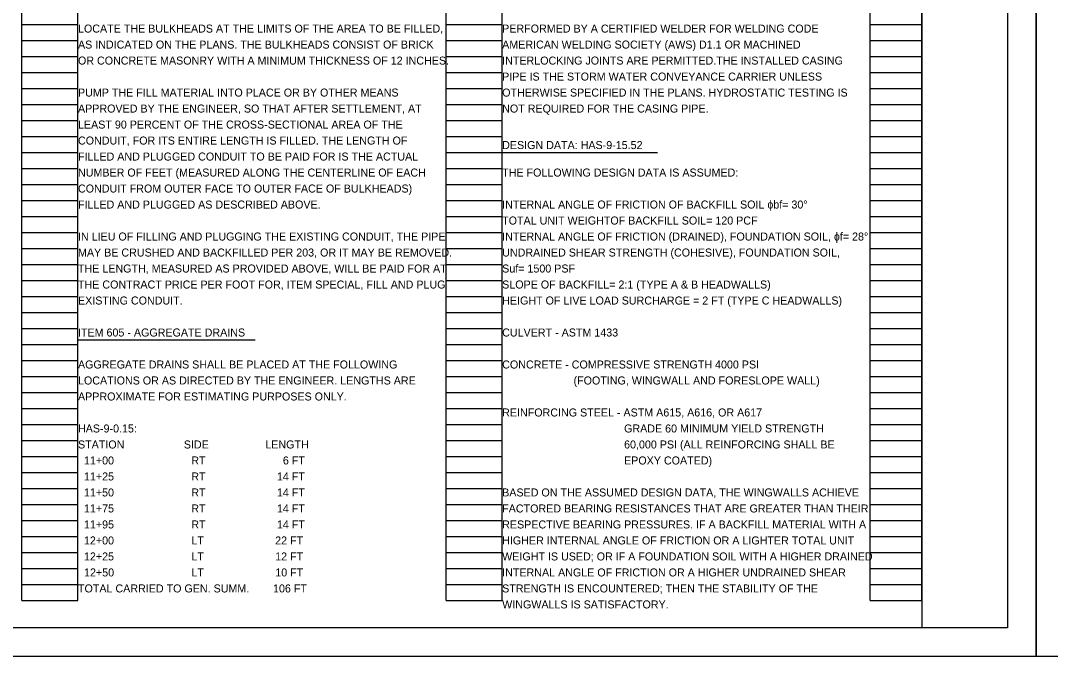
# Model space of a CAD drawing. Extents: x 0 to 102, y 0 to 22.
# Drawn here: x 50.24 to 68.25, y 0 to 11.13 of the extents above; entities that cross this region are included whole.
import ezdxf

# ---------------------------------------------------------------- set-up
doc = ezdxf.new("R2010")
doc.units = 0
doc.layers.add('SC_Scratch1', color=7, linetype='Continuous')
doc.layers.add('SH_Text', color=7, linetype='Continuous')

msp = doc.modelspace()

# ---------------------------------------------------------------- linework, layer by layer
at = {"layer": 'SC_Scratch1'}
for p, q in [((50.26, 0.98), (50.26, 21.14)), ((51.24, 0.98), (51.24, 21.14)), ((57.68, 0.98), (57.68, 21.14)), ((58.66, 0.98), (58.66, 21.14)), ((65.1, 0.98), (65.1, 21.14)), ((66, 0.98), (66, 21.14)), ((50.26, 11.06), (51.24, 11.06)), ((57.68, 11.06), (58.66, 11.06)), ((65.1, 11.06), (66, 11.06)), ((50.26, 10.78), (51.24, 10.78)), ((57.68, 10.78), (58.66, 10.78)), ((65.1, 10.78), (66, 10.78)), ((50.26, 10.5), (51.24, 10.5)), ((57.68, 10.5), (58.66, 10.5)), ((65.1, 10.5), (66, 10.5)), ((50.26, 10.22), (51.24, 10.22)), ((57.68, 10.22), (58.66, 10.22)), ((65.1, 10.22), (66, 10.22)), ((50.26, 9.94), (51.24, 9.94)), ((57.68, 9.94), (58.66, 9.94)), ((65.1, 9.94), (66, 9.94)), ((50.26, 9.66), (51.24, 9.66)), ((57.68, 9.66), (58.66, 9.66)), ((65.1, 9.66), (66, 9.66)), ((50.26, 9.38), (51.24, 9.38)), ((57.68, 9.38), (58.66, 9.38)), ((65.1, 9.38), (66, 9.38)), ((50.26, 9.1), (51.24, 9.1)), ((57.68, 9.1), (58.66, 9.1)), ((65.1, 9.1), (66, 9.1)), ((50.26, 8.82), (51.24, 8.82)), ((57.68, 8.82), (58.66, 8.82)), ((65.1, 8.82), (66, 8.82)), ((50.26, 8.54), (51.24, 8.54)), ((57.68, 8.54), (58.66, 8.54)), ((65.1, 8.54), (66, 8.54)), ((50.26, 8.26), (51.24, 8.26)), ((57.68, 8.26), (58.66, 8.26)), ((65.1, 8.26), (66, 8.26)), ((50.26, 7.98), (51.24, 7.98)), ((57.68, 7.98), (58.66, 7.98)), ((65.1, 7.98), (66, 7.98)), ((50.26, 7.7), (51.24, 7.7)), ((57.68, 7.7), (58.66, 7.7)), ((65.1, 7.7), (66, 7.7)), ((50.26, 7.42), (51.24, 7.42)), ((57.68, 7.42), (58.66, 7.42)), ((65.1, 7.42), (66, 7.42)), ((50.26, 7.14), (51.24, 7.14)), ((57.68, 7.14), (58.66, 7.14)), ((65.1, 7.14), (66, 7.14)), ((50.26, 6.86), (51.24, 6.86)), ((57.68, 6.86), (58.66, 6.86)), ((65.1, 6.86), (66, 6.86)), ((50.26, 6.58), (51.24, 6.58)), ((57.68, 6.58), (58.66, 6.58)), ((65.1, 6.58), (66, 6.58)), ((50.26, 6.3), (51.24, 6.3)), ((57.68, 6.3), (58.66, 6.3)), ((65.1, 6.3), (66, 6.3)), ((50.26, 6.02), (51.24, 6.02)), ((57.68, 6.02), (58.66, 6.02)), ((65.1, 6.02), (66, 6.02)), ((50.26, 5.74), (51.24, 5.74)), ((57.68, 5.74), (58.66, 5.74)), ((65.1, 5.74), (66, 5.74)), ((50.26, 5.46), (51.24, 5.46)), ((57.68, 5.46), (58.66, 5.46)), ((65.1, 5.46), (66, 5.46)), ((50.26, 5.18), (51.24, 5.18)), ((57.68, 5.18), (58.66, 5.18)), ((65.1, 5.18), (66, 5.18)), ((50.26, 4.9), (51.24, 4.9)), ((57.68, 4.9), (58.66, 4.9)), ((65.1, 4.9), (66, 4.9)), ((50.26, 4.62), (51.24, 4.62)), ((57.68, 4.62), (58.66, 4.62)), ((65.1, 4.62), (66, 4.62)), ((50.26, 4.34), (51.24, 4.34)), ((57.68, 4.34), (58.66, 4.34)), ((65.1, 4.34), (66, 4.34)), ((50.26, 4.06), (51.24, 4.06)), ((57.68, 4.06), (58.66, 4.06)), ((65.1, 4.06), (66, 4.06)), ((50.26, 3.78), (51.24, 3.78)), ((57.68, 3.78), (58.66, 3.78)), ((65.1, 3.78), (66, 3.78)), ((50.26, 3.5), (51.24, 3.5)), ((57.68, 3.5), (58.66, 3.5)), ((65.1, 3.5), (66, 3.5)), ((50.26, 3.22), (51.24, 3.22)), ((57.68, 3.22), (58.66, 3.22)), ((65.1, 3.22), (66, 3.22)), ((50.26, 2.94), (51.24, 2.94)), ((57.68, 2.94), (58.66, 2.94)), ((65.1, 2.94), (66, 2.94)), ((50.26, 2.66), (51.24, 2.66)), ((57.68, 2.66), (58.66, 2.66)), ((65.1, 2.66), (66, 2.66)), ((50.26, 2.38), (51.24, 2.38)), ((57.68, 2.38), (58.66, 2.38)), ((65.1, 2.38), (66, 2.38)), ((50.26, 2.1), (51.24, 2.1)), ((57.68, 2.1), (58.66, 2.1)), ((65.1, 2.1), (66, 2.1)), ((50.26, 1.82), (51.24, 1.82)), ((57.68, 1.82), (58.66, 1.82)), ((65.1, 1.82), (66, 1.82)), ((50.26, 1.54), (51.24, 1.54)), ((57.68, 1.54), (58.66, 1.54)), ((65.1, 1.54), (66, 1.54)), ((50.26, 1.26), (51.24, 1.26)), ((57.68, 1.26), (58.66, 1.26)), ((65.1, 1.26), (66, 1.26)), ((50.26, 0.98), (51.24, 0.98)), ((57.68, 0.98), (58.66, 0.98)), ((65.1, 0.98), (66, 0.98)), ((68, 0), (68, 0))]:
    msp.add_line(p, q, dxfattribs=at)
for points in [[(34, 22), (68, 22), (68, 0), (34, 0)], [(68, 22), (102, 22), (102, 0), (68, 0)], [(34.5, 21.5), (67.5, 21.5), (67.5, 0.5), (34.5, 0.5)], [(35.5, 21.5), (66, 21.5), (66, 0.5), (35.5, 0.5)]]:
    msp.add_lwpolyline(points, close=True, dxfattribs=at)
at = {"layer": 'SH_Text'}
for p, q in [((58.66, 8.82), (61.377, 8.82)), ((51.24, 5.539), (54.339, 5.539))]:
    msp.add_line(p, q, dxfattribs=at)

# ---------------------------------------------------------------- texts
for s, p in [('LOCATE THE BULKHEADS AT THE LIMITS OF THE AREA TO BE FILLED,', (51.24, 10.92)), ('PERFORMED BY A CERTIFIED WELDER FOR WELDING CODE ', (58.66, 10.92)), ('AS INDICATED ON THE PLANS. THE BULKHEADS CONSIST OF BRICK', (51.24, 10.64)), ('AMERICAN WELDING SOCIETY (AWS) D1.1 OR MACHINED ', (58.66, 10.64)), ('OR CONCRETE MASONRY WITH A MINIMUM THICKNESS OF 12 INCHES.', (51.24, 10.36)), ('INTERLOCKING JOINTS ARE PERMITTED.THE INSTALLED CASING ', (58.66, 10.36)), ('PIPE IS THE STORM WATER CONVEYANCE CARRIER UNLESS ', (58.66, 10.08)), ('PUMP THE FILL MATERIAL INTO PLACE OR BY OTHER MEANS', (51.24, 9.8)), ('OTHERWISE SPECIFIED IN THE PLANS. HYDROSTATIC TESTING IS ', (58.66, 9.8)), ('APPROVED BY THE ENGINEER, SO THAT AFTER SETTLEMENT, AT', (51.24, 9.52)), ('NOT REQUIRED FOR THE CASING PIPE.', (58.66, 9.52)), ('LEAST 90 PERCENT OF THE CROSS-SECTIONAL AREA OF THE', (51.24, 9.24)), ('CONDUIT, FOR ITS ENTIRE LENGTH IS FILLED. THE LENGTH OF', (51.24, 8.96)), ('DESIGN DATA: HAS-9-15.52 ', (58.66, 8.881)), ('FILLED AND PLUGGED CONDUIT TO BE PAID FOR IS THE ACTUAL', (51.24, 8.68)), ('NUMBER OF FEET (MEASURED ALONG THE CENTERLINE OF EACH', (51.24, 8.4)), ('THE FOLLOWING DESIGN DATA IS ASSUMED:', (58.66, 8.4)), ('CONDUIT FROM OUTER FACE TO OUTER FACE OF BULKHEADS)', (51.24, 8.12)), ('FILLED AND PLUGGED AS DESCRIBED ABOVE.', (51.24, 7.84)), ('INTERNAL ANGLE OF FRICTION OF BACKFILL SOIL ɸbf= 30°', (58.66, 7.84)), ('TOTAL UNIT WEIGHTOF BACKFILL SOIL= 120 PCF', (58.66, 7.56)), ('IN LIEU OF FILLING AND PLUGGING THE EXISTING CONDUIT, THE PIPE ', (51.24, 7.28)), ('INTERNAL ANGLE OF FRICTION (DRAINED), FOUNDATION SOIL, ɸf= 28°', (58.66, 7.28)), ('MAY BE CRUSHED AND BACKFILLED PER 203, OR IT MAY BE REMOVED. ', (51.24, 7)), ('UNDRAINED SHEAR STRENGTH (COHESIVE), FOUNDATION SOIL, ', (58.66, 7)), ('THE LENGTH, MEASURED AS PROVIDED ABOVE, WILL BE PAID FOR AT ', (51.24, 6.72)), ('Suf= 1500 PSF', (58.66, 6.72)), ('THE CONTRACT PRICE PER FOOT FOR, ITEM SPECIAL, FILL AND PLUG ', (51.24, 6.44)), ('SLOPE OF BACKFILL= 2:1 (TYPE A & B HEADWALLS)', (58.66, 6.44)), ('HEIGHT OF LIVE LOAD SURCHARGE = 2 FT (TYPE C HEADWALLS)', (58.66, 6.16)), ('EXISTING CONDUIT.', (51.24, 6.16)), ('ITEM 605 - AGGREGATE DRAINS', (51.24, 5.6)), ('CULVERT - ASTM 1433', (58.66, 5.6)), ('AGGREGATE DRAINS SHALL BE PLACED AT THE FOLLOWING ', (51.24, 5.04)), ('CONCRETE - COMPRESSIVE STRENGTH 4000 PSI', (58.66, 5.04)), ('LOCATIONS OR AS DIRECTED BY THE ENGINEER. LENGTHS ARE ', (51.24, 4.76)), ('                        (FOOTING, WINGWALL AND FORESLOPE WALL)', (58.66, 4.76)), ('APPROXIMATE FOR ESTIMATING PURPOSES ONLY.', (51.24, 4.48)), ('REINFORCING STEEL - ASTM A615, A616, OR A617', (58.66, 4.2)), ('HAS-9-0.15:', (51.24, 3.92)), ('                                         GRADE 60 MINIMUM YIELD STRENGTH', (58.66, 3.92)), ('                                         60,000 PSI (ALL REINFORCING SHALL BE ', (58.66, 3.64)), ('STATION                    SIDE                   LENGTH', (51.24, 3.64)), ('  11+00                          RT                          6 FT', (51.24, 3.36)), ('                                         EPOXY COATED)', (58.66, 3.36)), ('  11+25                          RT                        14 FT ', (51.24, 3.08)), ('  11+50                          RT                        14 FT ', (51.24, 2.8)), ('BASED ON THE ASSUMED DESIGN DATA, THE WINGWALLS ACHIEVE ', (58.66, 2.8)), ('  11+75                          RT                        14 FT', (51.24, 2.52)), ('FACTORED BEARING RESISTANCES THAT ARE GREATER THAN THEIR ', (58.66, 2.52)), ('  11+95                          RT                        14 FT', (51.24, 2.24)), ('RESPECTIVE BEARING PRESSURES. IF A BACKFILL MATERIAL WITH A ', (58.66, 2.24)), ('  12+00                          LT                        22 FT', (51.24, 1.96)), ('HIGHER INTERNAL ANGLE OF FRICTION OR A LIGHTER TOTAL UNIT ', (58.66, 1.96)), ('  12+25                          LT                        12 FT', (51.24, 1.68)), ('WEIGHT IS USED; OR IF A FOUNDATION SOIL WITH A HIGHER DRAINED ', (58.66, 1.68)), (' 12+50                          LT                        10 FT', (51.294, 1.4)), ('INTERNAL ANGLE OF FRICTION OR A HIGHER UNDRAINED SHEAR ', (58.66, 1.4)), ('TOTAL CARRIED TO GEN. SUMM.        106 FT', (51.24, 1.12)), ('STRENGTH IS ENCOUNTERED; THEN THE STABILITY OF THE ', (58.66, 1.12)), ('WINGWALLS IS SATISFACTORY.', (58.66, 0.84))]:
    msp.add_text(s, height=0.14, dxfattribs=at).set_placement(p)

doc.saveas('drawing.dxf')
